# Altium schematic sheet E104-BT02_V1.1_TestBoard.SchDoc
size A3
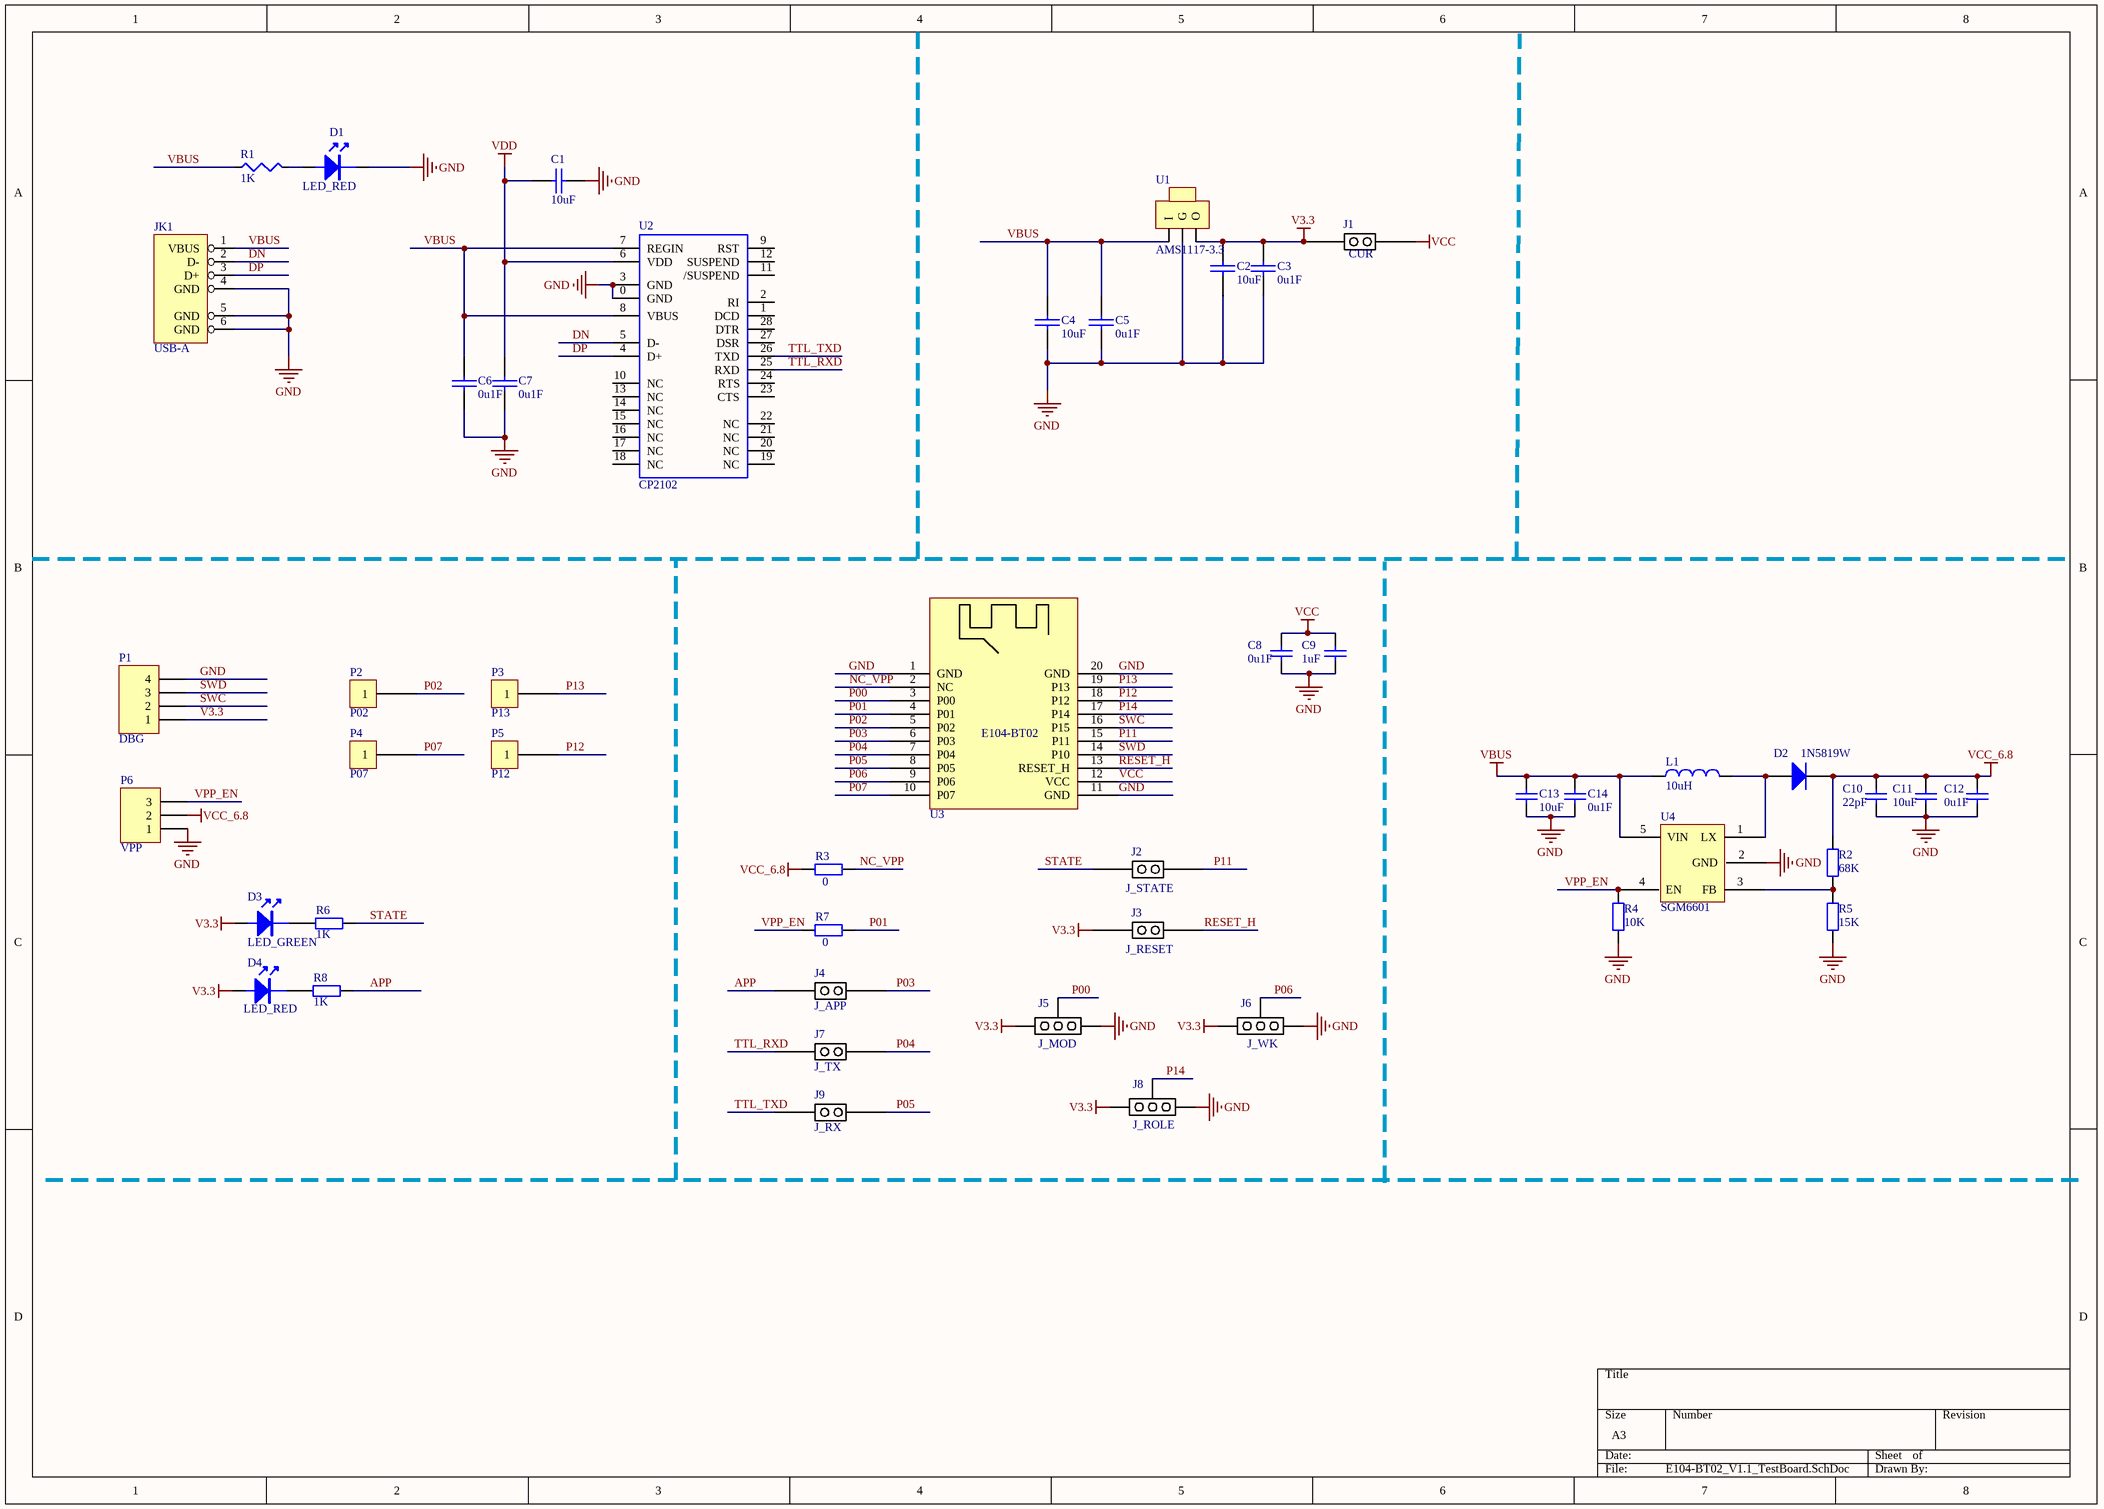
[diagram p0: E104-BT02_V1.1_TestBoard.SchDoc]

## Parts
C1  10uF  [CAP-0603]
C2  10uF  [CAP-0603]
C3  0u1F  [CAP-0603]
C4  10uF  [CAP-0603]
C5  0u1F  [CAP-0603]
C6  0u1F  [CAP-0603]
C7  0u1F  [CAP-0603]
C8  0u1F  [CAP-0603]
C9  1uF  [CAP-0603]
C10  22pF  [CAP-0603]
C11  10uF  [CAP-0603]
C12  0u1F  [CAP-0603]
C13  10uF  [CAP-0603]
C14  0u1F  [CAP-0603]
D1  LED_RED  [LED0805]
D2  1N5819W  [SOD-123]
D3  LED_GREEN  [LED0805]
D4  LED_RED  [LED0805]
J1  CUR  [HDR1X2]
J2  J_STATE  [HDR1X2]
J3  J_RESET  [HDR1X2]
J4  J_APP  [HDR1X2]
J5  J_MOD  [HDR1X3]
J6  J_WK  [HDR1X3]
J7  J_TX  [HDR1X2]
J8  J_ROLE  [HDR1X3]
J9  J_RX  [HDR1X2]
JK1  USB-A  [USB-AG-DIP]
L1  10uH  [NR3012]
P1  DBG  [HDR1X4]
P2  P02  [HDR1X1]
P3  P13  [HDR1X1]
P4  P07  [HDR1X1]
P5  P12  [HDR1X1]
P6  VPP  [HDR1X3]
R1  1K  [RES-0603]
R2  68K  [RES-0603]
R3  0  [RES-0603]
R4  10K  [RES-0603]
R5  15K  [RES-0603]
R6  1K  [RES-0603]
R7  0  [RES-0603]
R8  1K  [RES-0603]
U1  AMS1117-3.3  [SOT-223]
U2  CP2102  [QFN28-5X5-P0.5]
U3  E104-BT02_V1.1  [E104-BT02_V1.1]  (value not drawn)
U4  SGM6601  [TSOT-23-5]

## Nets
GND: C1.2 C2.2 C3.2 C4.2 C5.2 C6.2 C7.2 C8.2 C9.2 C10.2 C11.2 C12.2 C13.1 C14.1 D1.K J5.3 J6.3 J8.3 JK1.4(GND) JK1.5(GND) JK1.6(GND) P1.4 P6.1 R4.2 R5.1 U1.1(G) U2.0(GND) U2.3(GND) U3.1(GND) U3.11(GND) U3.20(GND) U4.2(GND)
V3.3: C2.1 C3.1 D3.A D4.A J1.1 J3.1 J5.1 J6.1 J8.1 P1.1 U1.2(O)
VBUS: C4.1 C5.1 C6.1 C13.2 C14.2 JK1.1(VBUS) L1.1 R1.1 U1.3(I) U2.7(REGIN) U2.8(VBUS) U4.5(VIN)
VCC: C8.1 C9.1 J1.2 U3.12(VCC)
VCC_6.8: C10.1 C11.1 C12.1 D2.2 P6.2 R2.2 R3.1
VDD: C1.1 C7.1 U2.6(VDD)
APP: J4.1 R8.1
DN: JK1.2(D-) U2.5(D-)
DP: JK1.3(D+) U2.4(D+)
NC_VPP: R3.2 U3.2(NC)
P00: J5.2 U3.3(P00)
P01: R7.2 U3.4(P01)
P02: P2.1 U3.5(P02)
P03: J4.2 U3.6(P03)
P04: J7.2 U3.7(P04)
P05: J9.2 U3.8(P05)
P06: J6.2 U3.9(P06)
P07: P4.1 U3.10(P07)
P11: J2.2 U3.15(P11)
P12: P5.1 U3.18(P12)
P13: P3.1 U3.19(P13)
P14: J8.2 U3.17(P14)
RESET_H: J3.2 U3.13(RESET_H)
STATE: J2.1 R6.1
SWC: P1.2 U3.16(P15)
SWD: P1.3 U3.14(P10)
TTL_RXD: J7.1 U2.25(RXD)
TTL_TXD: J9.1 U2.26(TXD)
VPP_EN: P6.3 R4.1 R7.1 U4.4(EN)
NetD1_A: D1.A R1.2
NetD2_1: D2.1 L1.2 U4.1(LX)
NetD3_K: D3.K R6.2
NetD4_K: D4.K R8.2
NetR2_1: R2.1 R5.2 U4.3(FB)

Not connected (* = marked no-connect by the designer): U2 1(DCD) 2(RI) 9(RST) 10(NC) 11(/SUSPEND) 12(SUSPEND) 13(NC) 14(NC) 15(NC) 16(NC) 17(NC) 18(NC) 19(NC) 20(NC) 21(NC) 22(NC) 23(CTS) 24(RTS) 27(DSR) 28(DTR)

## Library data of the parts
C1-C7 = cap0603: 0603
C8-C14 = Cap: 0603; Value: 0.01uF
D1 D3 D4 = LED: 0805
D2 = Diode: SOD-123
J1-J4 J7 J9 = JMP2: HDR1X2
J5 J6 J8 = JMP3: HDR1X3
JK1 = USB-A: USB-AG-DIP
L1 = Inductor: NR3012T100M; Code_IEC: 1005; Value: 10mH
P1 = Header 4H: HDR1X4
P2-P5 = Header 1H: HDR1X1
P6 = Header 3H: HDR1X3
R1 = res0603: 0603
R2-R8 = Res2: 0603; Value: 4K7
U1 = AMS1117-3.3: SOT-223
U2 = CP2102: QFN28-5X5-P0.5
U3 = E104-BT02
U4 = DCDC-SGM6601TTN5G/TR: TSOT-23-5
